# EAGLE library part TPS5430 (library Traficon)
3-A, WIDE INPUT RANGE, STEP-DOWN SWIFT? CONVERTER For SWIFT Documentation, Application Notes aid in quickly achieving high-performance power and Design Software, See the TI Website at supply designs to meet aggressive equipment www.ti.com/swift
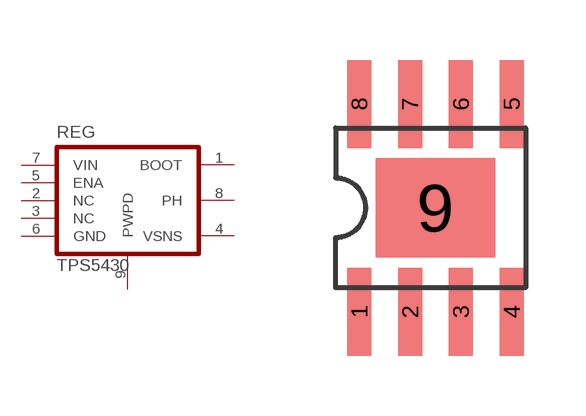
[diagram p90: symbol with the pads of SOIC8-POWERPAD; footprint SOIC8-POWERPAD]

Designator prefix REG

## TPS5430DDA  [SOIC8-POWERPAD]
1  BOOT
2  NC
3  NC
4  VSNS
5  ENA
6  GND
7  VIN
8  PH
9  PWPD

## Footprint SOIC8-POWERPAD (pad centres in mm)
smd 0.6 x 2.2: 1 -1.905,-2.6; 2 -0.635,-2.6; 3 0.635,-2.6; 4 1.905,-2.6; 5 1.905,2.6; 6 0.635,2.6; 7 -0.635,2.6; 8 -1.905,2.6
smd 2.997 x 2.489: 9 0,0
